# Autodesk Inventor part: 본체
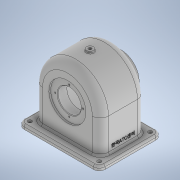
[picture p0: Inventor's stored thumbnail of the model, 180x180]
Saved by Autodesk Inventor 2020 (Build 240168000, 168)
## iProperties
Created: 2022-09
Part Number: 본체
Material: 일반
Document SubType Name: Modeling
Designer: Administrator
Density: 1 g/cm^3
Appearance: 기본값
Mass: 455.436 g
Surface Area: 1085.58 cm^2
Volume: 455.436 cm^3
Author: Administrator
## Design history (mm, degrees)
sketch "스케치1"
  geometry: L1 (-70, 54)-(70, 54); L2 (70, 54)-(70, -54); L3 (70, -54)-(-70, -54); L4 (-70, -54)-(-70, 54); L5 (-70, 54)-(70, -54); L6 (70, 54)-(-70, -54); 1 further point
  constraints: 12 end point, 2 midpoint, 2 parallel, 1 horizontal, 1 perpendicular
  dimensions: "d0" = 140 distance of L1.start L1.end; "d1" = 108 distance of L3.end L1.start
extrude "돌출1" new body sketch "스케치1" distance "d2" = 7; taper "d3" = 0 deg
fillet "모깎기1" dims "d4" = 10
sketch "스케치2"
  geometry: C1 r 3.3 at (60, -44); A1 r 10 centre (60, -44) between (60, -54) and (70, -44) reference; 1 further point
  constraints: 1 centre point, 1 coincident
  dimensions: "d5" = 6.6 diameter of C1
extrude "돌출2" cut sketch "스케치2" extent not by distance; stored distance "d6" = 0; taper "d7" = 0 deg
sketch "스케치3"
  geometry: L1 (-60, 7)-(60, 7) reference; L2 (57, 64)-(57, 7); L3 (-57, 64)-(-57, 7); A1 r 57 centre (0, 64) between (57, 64) and (-57, 64); 1 further point
  constraints: 4 end point, 2 perpendicular, 2 point on circle, 2 point on line, 2 tangent, 1 centre point, 1 vertical alignment
  dimensions: "d12" = 57 radius of A1; "d13" = 64 distance of point (0, 0) A1.centre
extrude "돌출3" join sketch "스케치3" stored distance "d15" = 78; taper "d16" = 0 deg
node "작업 평면1"
sketch "스케치5"
  geometry: C1 r 6 at (0, 0); 1 further point
  constraints: 1 centre point, 1 coincident
  dimensions: "d22" = 12 diameter of C1
extrude "돌출5" join sketch "스케치5" stored distance "d23" = 68; taper "d24" = 0 deg
sketch "스케치7"
  geometry: C1 r 31 at (0, -64); A1 r 57 centre (0, -64) between (-57, -64) and (57, -64) reference; 1 further point
  constraints: 1 centre point, 1 coincident
  dimensions: "d25" = 62 diameter of C1
extrude "돌출6" join sketch "스케치7" distance "d26" = 15; taper "d27" = 0 deg
sketch "스케치8"
  geometry: L1 (-39, 64)-(64.281, 64); L2 (-39, 64)-(-39, 96); L3 (-39, 96)-(-36, 96); L4 (-36, 96)-(-36, 84); L5 (-36, 84)-(-20, 84); L6 (-20, 84)-(-20, 92); L7 (-20, 92)-(-34, 100.083); L8 (-34, 100.083)-(-34, 116); L9 (-34, 116)-(34, 116); L10 (34, 116)-(34, 81.5); L11 (34, 81.5)-(38, 81.5); L12 (38, 81.5)-(38, 84); L13 (54, 33)-(54, 95) reference; L14 (38, 84)-(54, 84); L15 (54, 64)-(54, 84); L16 (39, 64)-(39, 121) reference; L17 (-39, 121)-(39, 121) reference; L18 (-39, 121)-(-39, 64) reference; 2 further points
  constraints: 28 end point, 9 perpendicular, 2 vertical, 1 collinear, 1 horizontal, 1 midpoint, 1 point on line
  dimensions: "d28" = 16 distance of L4.end L5.end; "d29" = 16 distance of L12.end L14.end; "d30" = 40 diameter of L14 L1; "d31" = 35 diameter of L11 L1; "d32" = 5 distance between parallel lines of L16 L10; "d34" = 5 distance between parallel lines of L17 L9; "d35" = 5 distance between parallel lines of L18 L8; "d36" = 60 deg angle of L6 L7; "d37" = 56 diameter of L6.end L1; "d38" = 14 horizontal distance of L6.end L8.end; "d39" = 40 diameter of L5 L1; "d40" = 64 diameter of L3 L1
revolve "회전1" sketch "스케치8" stored, may be unused: angle "d41" = 90 deg
chamfer "모따기1" distance "d42" = 1; stored, may be unused: second distance "d43" = 2, angle "d44" = 45 deg
fillet "모깎기2" dims "d45" = 3
sketch "스케치9"
  geometry: C1 r 6 at (0, 0) reference; 2 further points
  constraints: 1 coincident
hole "구멍1" sketch "스케치9" at (0, 0) diameter "d46" = 5.1881; stored, may be unused: countersink angle "d50" = 90 deg, drill point angle "d52" = 0 deg; dims "d47" = 12, "d48" = 4, "d49" = 2, "d51" = 8
fillet "모깎기3" dims "d53" = 1
fillet "모깎기4" dims "d54" = 14
fillet "모깎기5" dims "d55" = 3
sketch "스케치10"
  geometry: L1 (64, -19)-(64, 69) reference; L2 (0, -14)-(54, -14) reference; 3 further points
  constraints: 1 horizontal alignment, 1 midpoint, 1 other
  dimensions: "d56" = 17 distance from line of L1 point (47, 25); "d84" = 39 distance from line of L2 point (47, 25) (derived)
feature "엠보싱1" sketch "스케치10" dims "d0" = 140, "d1" = 108, "d57" = 0.5, "d58" = 0
sketch "스케치11" dims "d59" = 48
  geometry: C1 r 21 at (0, 0) reference; 3 further points
  constraints: 1 coincident, 1 vertical alignment, 2 other
hole "구멍2" sketch "스케치11" at (0, -24) diameter "d60" = 2.459; stored, may be unused: countersink angle "d64" = 90 deg, drill point angle "d66" = 118 deg; dims "d61" = 7, "d62" = 4, "d63" = 2, "d65" = 9
sketch "스케치12" dims "d70" = 48
  geometry: C1 r 21 at (0, 0) reference; 3 further points
  constraints: 1 coincident, 1 vertical alignment, 2 other
hole "구멍3" sketch "스케치12" at (0, 24) diameter "d71" = 2.459; stored, may be unused: countersink angle "d75" = 90 deg, drill point angle "d77" = 118 deg; dims "d72" = 7, "d73" = 4, "d74" = 2, "d76" = 9
fillet "모깎기6" dims "d81" = 9
fillet "모깎기7" dims "d82" = 3, "d83" = 0.6
fillet "모깎기8" dims "d85" = 3
node "솔리드1"
pattern_linear "직사각형 패턴1"
pattern_circular "원형 패턴1" dims angle "d68" = 360 deg
pattern_circular "원형 패턴2" dims angle "d79" = 360 deg
feature "A9D066F2-1C7D-4E18-AEED-F7BC21143FA4" dims "d60" = 2.459, "d61" = 7, "d62" = 4, "d63" = 2, "d64" = 90 deg, "d65" = 9, "d66" = 118 deg
other parameters: "d21" = 124
